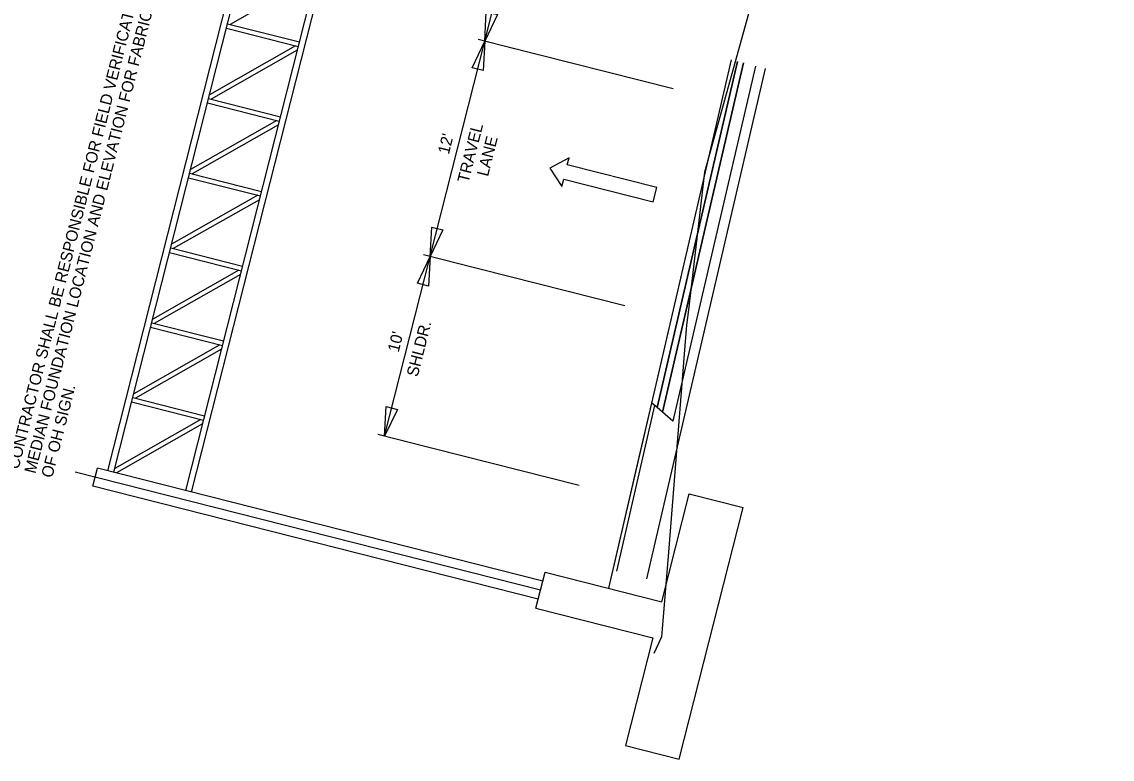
# Model space of a CAD drawing. Extents: x 670003 to 670131, y 737835 to 738003.
# Drawn here: x 670053.1 to 670112, y 737835.3 to 737875 of the extents above; entities that cross this region are included whole.
import ezdxf

# ---------------------------------------------------------------- set-up
doc = ezdxf.new("R2010")
doc.units = 0
for name, color, linetype in [('R_Alt Surface', 7, 'Continuous'), ('R_Exist Surface', 7, 'Continuous'), ('R_MOT', 7, 'Continuous'), ('R_SIGN', 7, 'Continuous'), ('R_SIGN_ANNOT', 7, 'Continuous')]:
    doc.layers.add(name, color=color, linetype=linetype)

msp = doc.modelspace()

# ---------------------------------------------------------------- linework, layer by layer
at = {"layer": 'R_Alt Surface'}
for p, q in [((670087.156, 737854.473), (670091.458, 737872.983)), ((670091.778, 737872.902), (670087.438, 737854.229)), ((670087.438, 737854.229), (670091.778, 737872.902)), ((670087.72, 737853.986), (670092.098, 737872.821)), ((670092.098, 737872.821), (670087.72, 737853.986)), ((670092.744, 737872.657), (670088.287, 737853.496)), ((670093.269, 737872.524), (670088.81, 737853.364)), ((670087.156, 737854.473), (670088.741, 737861.292)), ((670084.833, 737844.483), (670087.156, 737854.473)), ((670087.297, 737854.351), (670085.241, 737845.411)), ((670086.476, 737851.55), (670087.156, 737854.473)), ((670087.438, 737854.229), (670087.156, 737854.473)), ((670087.72, 737853.986), (670087.438, 737854.229)), ((670088.287, 737853.496), (670087.72, 737853.986)), ((670088.81, 737853.364), (670086.864, 737844.999)), ((670084.833, 737844.483), (670086.476, 737851.55))]:
    msp.add_line(p, q, dxfattribs=at)
at = {"layer": 'R_Exist Surface'}
msp.add_lwpolyline([(670106.502, 737955.962), (670111.377, 737932.926), (670111.492, 737932.435), (670111.496, 737932.423), (670111.755, 737931.399), (670111.997, 737930.453), (670111.984, 737930.402), (670111.022, 737926.655), (670110.931, 737926.545), (670109.565, 737925.004), (670103.151, 737910.71), (670100.52, 737904.756), (670095.739, 737887.589), (670089.988, 737866.935), (670089.122, 737859.498), (670089.026, 737858.686), (670088.894, 737857.106), (670088.049, 737846.436), (670087.716, 737842.296), (670087.676, 737841.874), (670087.513, 737841.506), (670087.265, 737840.962)], dxfattribs=at)
at = {"layer": 'R_MOT'}
for p, q in [((670082.689, 737867.712), (670081.643, 737867.152)), ((670082.591, 737867.324), (670082.689, 737867.712)), ((670081.643, 737867.152), (670082.296, 737866.162)), ((670087.429, 737866.097), (670082.591, 737867.324)), ((670082.296, 737866.162), (670082.394, 737866.55)), ((670082.394, 737866.55), (670087.232, 737865.323)), ((670087.232, 737865.323), (670087.429, 737866.097))]:
    msp.add_line(p, q, dxfattribs=at)
at = {"layer": 'R_SIGN'}
for p, q in [((670057.793, 737850.825), (670065.417, 737880.888)), ((670058.116, 737850.743), (670065.741, 737880.806)), ((670061.993, 737849.76), (670069.618, 737879.823)), ((670062.316, 737849.678), (670069.941, 737879.741)), ((670069.041, 737877.547), (670064.393, 737874.906)), ((670064.192, 737874.699), (670068.069, 737873.716)), ((670064.253, 737874.941), (670068.13, 737873.958)), ((670067.929, 737873.751), (670063.281, 737871.11)), ((670068.018, 737873.514), (670063.37, 737870.873)), ((670063.169, 737870.666), (670067.046, 737869.683)), ((670063.23, 737870.908), (670067.108, 737869.925)), ((670066.907, 737869.718), (670062.259, 737867.077)), ((670066.995, 737869.481), (670062.347, 737866.84)), ((670062.207, 737866.875), (670066.085, 737865.892)), ((670062.146, 737866.633), (670066.023, 737865.649)), ((670065.884, 737865.685), (670061.236, 737863.044)), ((670065.972, 737865.448), (670061.324, 737862.807)), ((670061.185, 737862.842), (670065.062, 737861.859)), ((670061.123, 737862.6), (670065, 737861.616)), ((670064.861, 737861.652), (670060.213, 737859.011)), ((670064.949, 737861.414), (670060.301, 737858.774)), ((670060.162, 737858.809), (670064.039, 737857.826)), ((670060.1, 737858.567), (670063.977, 737857.583)), ((670063.838, 737857.619), (670059.19, 737854.978)), ((670063.926, 737857.381), (670059.278, 737854.741)), ((670059.077, 737854.534), (670062.955, 737853.55)), ((670059.139, 737854.776), (670063.016, 737853.793)), ((670062.815, 737853.586), (670058.167, 737850.945)), ((670062.903, 737853.348), (670058.255, 737850.708)), ((670056.981, 737849.999), (670057.227, 737850.968)), ((670081.267, 737844.871), (670057.227, 737850.968)), ((670081.144, 737844.387), (670056.038, 737850.754)), ((670081.021, 737843.902), (670056.981, 737849.999)), ((670087.69, 737843.758), (670089.165, 737849.574)), ((670089.165, 737849.574), (670092.073, 737848.836)), ((670088.631, 737835.266), (670092.073, 737848.836)), ((670080.898, 737843.417), (670081.39, 737845.356)), ((670081.39, 737845.356), (670087.69, 737843.758)), ((670080.898, 737843.417), (670087.198, 737841.819)), ((670087.198, 737841.819), (670085.723, 737836.004)), ((670085.723, 737836.004), (670088.631, 737835.266))]:
    msp.add_line(p, q, dxfattribs=at)
at = {"layer": 'R_SIGN_ANNOT'}
for p, q in [((670078.136, 737873.998), (670081.083, 737885.619)), ((670075.189, 737862.377), (670078.136, 737873.998)), ((670079.747, 737873.589), (670077.773, 737874.09)), ((670088.306, 737871.419), (670079.178, 737873.734)), ((670072.732, 737852.694), (670075.189, 737862.377)), ((670076.8, 737861.969), (670074.825, 737862.47)), ((670085.686, 737859.715), (670076.231, 737862.113)), ((670074.344, 737852.285), (670072.369, 737852.786)), ((670083.23, 737850.031), (670073.775, 737852.429))]:
    msp.add_line(p, q, dxfattribs=at)
for points in [[(670078.822, 737875.434), (670078.136, 737873.998), (670078.217, 737875.588)], [(670077.449, 737872.562), (670078.136, 737873.998), (670078.055, 737872.408)], [(670075.875, 737863.814), (670075.189, 737862.377), (670075.27, 737863.967)], [(670074.502, 737860.941), (670075.189, 737862.377), (670075.107, 737860.788)], [(670073.419, 737854.13), (670072.732, 737852.694), (670072.814, 737854.283)]]:
    msp.add_lwpolyline(points, close=True, dxfattribs=at)

# ---------------------------------------------------------------- texts
at = {"layer": 'R_SIGN'}
for s, p in [('CONTRACTOR SHALL BE RESPONSIBLE FOR FIELD VERIFICATION OF', (670052.971, 737850.867)), ('MEDIAN FOUNDATION LOCATION AND ELEVATION FOR FABRICATION', (670053.879, 737850.636)), ('OF OH SIGN.', (670054.788, 737850.406))]:
    msp.add_text(s, height=0.625, rotation=75.76855, dxfattribs=at).set_placement(p)
at = {"layer": 'R_SIGN_ANNOT'}
for s, p in [('TRAVEL', (670077.251, 737866.317)), ("12'", (670076.194, 737867.86)), ('LANE', (670078.306, 737866.664)), ('SHLDR.', (670074.51, 737855.854)), ("10'", (670073.486, 737857.184))]:
    msp.add_text(s, height=0.625, rotation=75.76855, dxfattribs=at).set_placement(p)

doc.saveas('drawing.dxf')
